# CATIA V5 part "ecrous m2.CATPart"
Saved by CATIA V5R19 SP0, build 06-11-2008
Part number: ecrous m.2
Bounding box of the stored display mesh (mm): x 0 to 1.2, y -1.877 to 1.877, z -2.16 to 2.16
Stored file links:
  I:\mediator\ecrous m2.CATPart
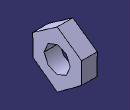
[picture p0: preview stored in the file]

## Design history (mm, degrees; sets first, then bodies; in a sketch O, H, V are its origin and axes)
Body1 (main body)
  Sketch1 on yz-plane, origin (0, 0, 0), H (0, 1, 0), V (0, 0, 1)
    point P1 (1.876, -0.7805)
    line L1 (1.876, -0.7805) -> (1.8774, 0.8512)
    point P2 (1.8774, 0.8512)
    line L2 (1.8774, 0.8512) -> (0, 2.16)
    point P3 (0, 2.16)
    line L3 (1.876, -0.7805) -> (0, -2.16)
    point P4 (0, -2.16)
    axis line L4 (0, 2.16) -> (0, -2.16)
    point P5 (0, 2.16)
    point P7 (0, -2.16)
    point P8 (-1.876, -0.7805)
    line L5 (-1.876, -0.7805) -> (0, -2.16)
    point P9 (-1.8774, 0.8512)
    line L6 (-1.876, -0.7805) -> (-1.8774, 0.8512)
    point P10 (0, 2.16)
    line L7 (-1.8774, 0.8512) -> (0, 2.16)
    coincidence: P3 V, P4 V, P5 L2, P3 P10, P4 P7
    vertical: L4 V
    symmetry: P4 P7 L4, P1 P8 L4, L3 L5 L4, P2 P9 L4, L1 L6 L4, P3 P10 L4, L2 L7 L4
  Pad1: profile Sketch1, direction (1, 0, 0), length 1.2
  Sketch2 on end face of Pad1, origin (1.2, 0, 0), H (0, 1, 0), V (0, 0, 1)
    circle A1 centre (0, 0) radius 1
    radius A1 = 1
  Pocket1: profile Sketch2, direction (-1, 0, 0), length 1.2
